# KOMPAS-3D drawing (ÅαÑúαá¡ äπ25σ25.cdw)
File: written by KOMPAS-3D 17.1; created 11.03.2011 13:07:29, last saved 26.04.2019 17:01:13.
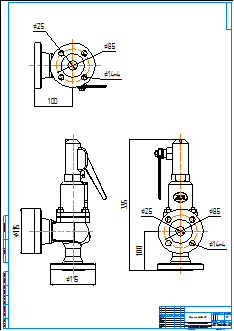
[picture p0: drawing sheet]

Sheet 1: A1, portrait

Title block, sheet 1: name: Прегран Ду25х25; material: Внимание! Данный продукт является объектом авторского права ООО «Торговый Дом АДЛ». / Запрещается изменение, копирование, распространение / (в том числе путем копирования на другие сайты и ресурсы в Интернете) / или любое иное использование информации и объектов без предварительного / согласия правообладателя (ООО «Торговый Дом АДЛ»).; scale: 1:1; sheets: 1; organisation: ООО "Торговый дом АДЛ"; sheet format: A1; stored path: C:\Users\tra\Desktop\2д чертежи\Предохранительные клапаны ПРЕГРАН\ПРЕГРАН 096\ПРЕГРАН КПП 096-03-40\KOMPAS 2D\Прегран Ду25х25.cdw

Views: Спереди 1, Проекционный вид 2, Проекционный вид 3
Dimensions and other numbers on the sheet: 85; 14; 25; 100; 335; 115; 1:1; 1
